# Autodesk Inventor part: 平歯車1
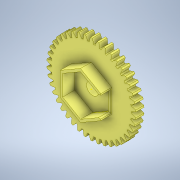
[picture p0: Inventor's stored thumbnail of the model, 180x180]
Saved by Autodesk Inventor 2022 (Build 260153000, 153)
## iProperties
CustomPartVersion: 1
Created: 2024-11
Part Number: 平歯車1
Material: Steel
Document SubType Name: Modeling
Designer: neo09
Categories: <?xml version="1.0" encoding="UTF-16"?> <MemberInstance><Categories><FamilyTemplate><FamilyTemplateParameter ValueType="xs:double" Id="1" ObjectReferenceKey="da
Density: 1 g/cm^3
Appearance: Steel
Author: neo09
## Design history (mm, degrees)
sketch "Sketch1"
  geometry: C1 r 11 at (0, 0)
  constraints: 1 centre point
  dimensions: "d0" = 22 diameter of C1 (= da_da)
extrude "Extrusion1" new body sketch "Sketch1" distance "d1" = 2 (= da_b); taper "d2" = 0 deg
workplane "Work Plane2"
sketch "Sketch2"
  geometry: C1 r 11 at (0, 0) reference; C2 r 10.5 at (0, 0)
  constraints: 1 centre point, 1 coincident
  dimensions: "d3" = 21 diameter of C2 (= da_d)
feature "ピッチ円直径" sketch "Sketch2" dims "d4" = 10, "d5" = 0
workplane "Work Plane8"
workplane "Work Plane9"
feature "平歯車" dims "da_b" = 2, "da_d" = 21, "da_aw" = 24.75, "da_da" = 22, "da_df" = 19.75, "da_dw" = 21, angle "da_beta" = 0 deg, "da_lefttooth" = 0, "da_righttooth" = 0
sketch "スケッチ3"
  geometry: L1 (0, 5.774)-(5, 2.887); L2 (5, -2.887)-(0, -5.774); L3 (0, -5.774)-(-5, -2.887); L4 (-5, -2.887)-(-5, 2.887); L5 (-5, 2.887)-(0, 5.774); L6 (0, 5.081)-(4.4, 2.54); L7 (4.4, -2.54)-(0, -5.081); L8 (0, -5.081)-(-4.4, -2.54); L9 (-4.4, -2.54)-(-4.4, 2.54); L10 (-4.4, 2.54)-(0, 5.081); L11 (4.4, 2.54)-(5, 2.54); L12 (4.4, -2.54)-(5, -2.54); L13 (5, 2.887)-(5, 2.54); L14 (5, -2.54)-(5, -2.887); 4 further points
  constraints: 28 end point, 2 coincident, 2 perpendicular, 1 horizontal, 22 other
  dimensions: "d49" = 10 distance between parallel lines of L3 L1; "d50" = 8.8 distance between parallel lines of L7 L10
extrude "押し出し2" join sketch "スケッチ3" distance "d51" = 2.7; taper "d52" = 0 deg
sketch "スケッチ4"
  geometry: L1 (0, 5.081)-(-4.4, 2.54) reference; L2 (0, 5.081)-(4.4, 2.54); L3 (4.4, 2.54)-(4.4, -2.54); L4 (4.4, -2.54)-(0, -5.081); L5 (0, -5.081)-(-4.4, -2.54); L6 (-4.4, -2.54)-(-4.4, 2.54); L7 (-4.4, 2.54)-(0, 5.081); 3 further points
  constraints: 12 end point, 1 coincident, 13 other
extrude "押し出し3" cut sketch "スケッチ4" distance "d53" = 0.3; taper "d54" = 0 deg
sketch "スケッチ8"
  geometry: L1 (4.4, 2.54)-(4.4, -2.54) reference; L2 (4.4, 2.54)-(5, 2.54) reference; L3 (4.4, 2.54)-(5, 2.54); L4 (5, -2.54)-(4.4, -2.54) reference; L5 (5, 2.54)-(5, -2.54); L6 (5, -2.54)-(4.4, -2.54); L7 (0, 5.081)-(4.4, 2.54) reference; L8 (4.4, -2.54)-(4.4, 2.54); 1 further point
  constraints: 8 end point, 3 perpendicular, 1 collinear
extrude "押し出し4" join sketch "スケッチ8" distance "d55" = 0.2; taper "d56" = 0 deg
sketch "スケッチ9"
  geometry: C1 r 1.5 at (0, 0); 1 further point
  constraints: 1 centre point, 1 coincident
  dimensions: "d57" = 3 diameter of C1
extrude "押し出し5" cut sketch "スケッチ9" distance "d58" = 3; taper "d59" = 0 deg
body "Solid1"
sketch "スケッチ5"
  geometry: L1 (4.4, 2.54)-(5, 2.54) reference; L2 (5, -2.54)-(4.4, -2.54) reference; 1 further point
sketch "スケッチ6"
  geometry: L1 (4.4, 2.54)-(4.4, -2.54) reference; L2 (0, 5.081)-(4.4, 2.54) reference; L3 (4.4, 2.54)-(5, 2.54) reference; L4 (5, -2.54)-(4.4, -2.54) reference; L5 (4.4, -2.54)-(0, -5.081) reference; 1 further point
sketch "スケッチ7"
  geometry: 1 further point
body "Srf1"
other parameters: "d16" = 24.75 (= da_aw), "d17" = 0, "d34" = 0.748 (computed from da_z), "d39" = 0, "d41" = 0, "d43" = 24.75 (= da_aw), "d46" = 24.75 (= da_aw), "d47" = 0, "d48" = 0
